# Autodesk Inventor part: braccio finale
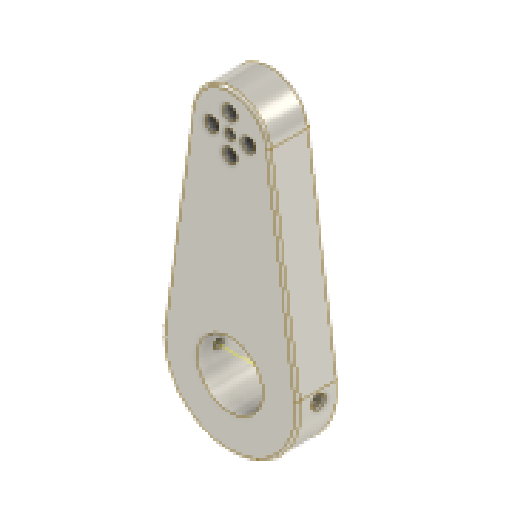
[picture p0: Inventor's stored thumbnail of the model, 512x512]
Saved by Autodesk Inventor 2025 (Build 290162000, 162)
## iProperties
Created: 2025-05
Part Number: braccio finale
Material: Titanio
Document SubType Name: Modeling
Designer: Ryzen5700u
Density: 4.51 g/cm^3
Appearance: Titanio
Author: Ryzen5700u
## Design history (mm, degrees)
sketch "Schizzo1"
  geometry: L1 (-25.751, 3.591)-(-14.807, 82.072); L2 (25.755, 3.559)-(14.908, 82.053); C1 r 12.55 at (0, 0); C2 r 2 at (0.049, 80); A1 r 26 centre (0, 0) between (25.755, 3.559) and (-25.751, 3.591); A2 r 15 centre (0.049, 80) between (-14.807, 82.072) and (14.908, 82.053); 2 further points
  constraints: 4 centre point, 4 coincident, 4 end point, 4 point on circle, 4 tangent
  dimensions: "d0" = 52 diameter of A1; "d2" = 25.1 diameter of C1; "d28" = 4 diameter of C2; "d29" = 30 diameter of A2; "d30" = 80 distance of point (0.049, 80) point (0, 0)
extrude "Estrusione1" new body sketch "Schizzo1" distance "d3" = 16; taper "d4" = 0 deg
fillet "Raccordo1" dims "d5" = 1
sketch "Schizzo5"
  geometry: C1 r 2 at (-0.049, 80) reference; 2 further points
  constraints: 1 coincident
hole "Foro4" sketch "Schizzo5" at (-0.049, 80) diameter "d31" = 3.4; stored, may be unused: countersink angle "d35" = 90 deg, drill point angle "d37" = 118 deg; dims "d32" = 6, "d33" = 7, "d34" = 5, "d36" = 8
sketch "Schizzo6"
  geometry: L1 (-12.55, 16)-(12.55, 16) reference; C1 r 1.6 at (0, 8); 2 further points
  constraints: 1 centre point, 1 coincident
  dimensions: "d38" = 8 distance from line of L1 point (0, 8); "d39" = 3.2 diameter of C1
extrude "Estrusione2" cut sketch "Schizzo6" extent not by distance; stored distance "d40" = 0; taper "d41" = 0 deg
node "Asse di lavoro1"
node "Piano di lavoro1"
sketch "Schizzo7"
  geometry: 4 further points
  constraints: 1 vertical alignment
hole "Foro5" sketch "Schizzo7" at (0, 8) diameter "d43" = 3.4; stored, may be unused: countersink angle "d47" = 90 deg, drill point angle "d49" = 118 deg; dims "d44" = 6, "d45" = 6, "d46" = 2, "d48" = 8
mirror "Speculare1"
fillet "Raccordo2" dims "d50" = 1
sketch "Schizzo9"
  geometry: L1 (13.917, 81.916)-(24.765, 3.422) reference; L2 (-24.76, 3.453)-(-13.817, 81.934) reference; C1 r 2 at (0.049, 80) reference; C2 r 12.55 at (0, 0) reference; C3 r 1.6 at (0.049, 73) reference; C4 r 1.6 at (0.049, 87) reference; C5 r 1.6 at (7.049, 80) reference; C6 r 1.6 at (-6.951, 80) reference; A1 r 25 centre (0, 0) between (-24.76, 3.453) and (24.765, 3.422) reference; A2 r 14 centre (0.049, 80) between (13.917, 81.916) and (-13.817, 81.934) reference; 1 further point
hole "Foro6" sketch "Schizzo9" at (-6.951, 80), (0.049, 73), (7.049, 80), (0.049, 87) diameter "d51" = 3.2; stored, may be unused: countersink angle "d55" = 90 deg, drill point angle "d57" = 118 deg; dims "d52" = 6, "d53" = 5.5, "d54" = 4, "d56" = 8
sketch "Schizzo11"
  geometry: C1 r 13.5 at (0, 0); C2 r 12.55 at (0, 0) reference; A1 r 26 centre (0, 0) between (-25.755, 3.559) and (25.751, 3.591) reference; 1 further point
  constraints: 1 centre point, 1 coincident
  dimensions: "d58" = 27 diameter of C1
extrude "Estrusione3" join sketch "Schizzo11" distance "d59" = 4; taper "d60" = 0 deg
node "Piano di lavoro2"
sketch "Schizzo12"
  geometry: C1 r 1.7 at (0, 8) reference; 2 further points
  constraints: 1 coincident
hole "Foro7" sketch "Schizzo12" at (0, 8) diameter "d62" = 3.4; stored, may be unused: countersink angle "d66" = 90 deg, drill point angle "d68" = 118 deg; dims "d63" = 6, "d64" = 5.5, "d65" = 4, "d67" = 8
node "Piano di lavoro3"
sketch "Schizzo13"
  geometry: L1 (-3.233, 8)-(-1.617, 10.8); L2 (-1.617, 10.8)-(1.617, 10.8); L3 (1.617, 10.8)-(3.233, 8); L4 (3.233, 8)-(1.617, 5.2); L5 (1.617, 5.2)-(-1.617, 5.2); L6 (-1.617, 5.2)-(-3.233, 8); C1 r 1.7 at (0, 8) reference; 3 further points
  constraints: 12 end point, 2 coincident, 13 other
  dimensions: "d70" = 5.6 distance between parallel lines of L5 L2
extrude "Estrusione4" cut sketch "Schizzo13" distance "d71" = 5; taper "d72" = 0 deg
fillet "Raccordo3" dims "d73" = 2
node "Solido1"
node "Linea chiusa proiettata1"
node "Riferimento9"
node "Riferimento10"
node "Riferimento11"
node "Riferimento12"
other parameters: "d42" = 21, "d61" = 28.5, "d69" = -28.5
